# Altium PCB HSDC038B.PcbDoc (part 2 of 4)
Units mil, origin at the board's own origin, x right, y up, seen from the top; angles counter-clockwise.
Board outline 3620 x 4060 mil, 6 copper layers (Top Layer, Signal Layer 1, Signal Layer 2, Signal Layer 3, Signal Layer 4, Bottom Layer), stack 60.4 mil thick; 349 components, 209 nets, 1023 pads, 960 vias.
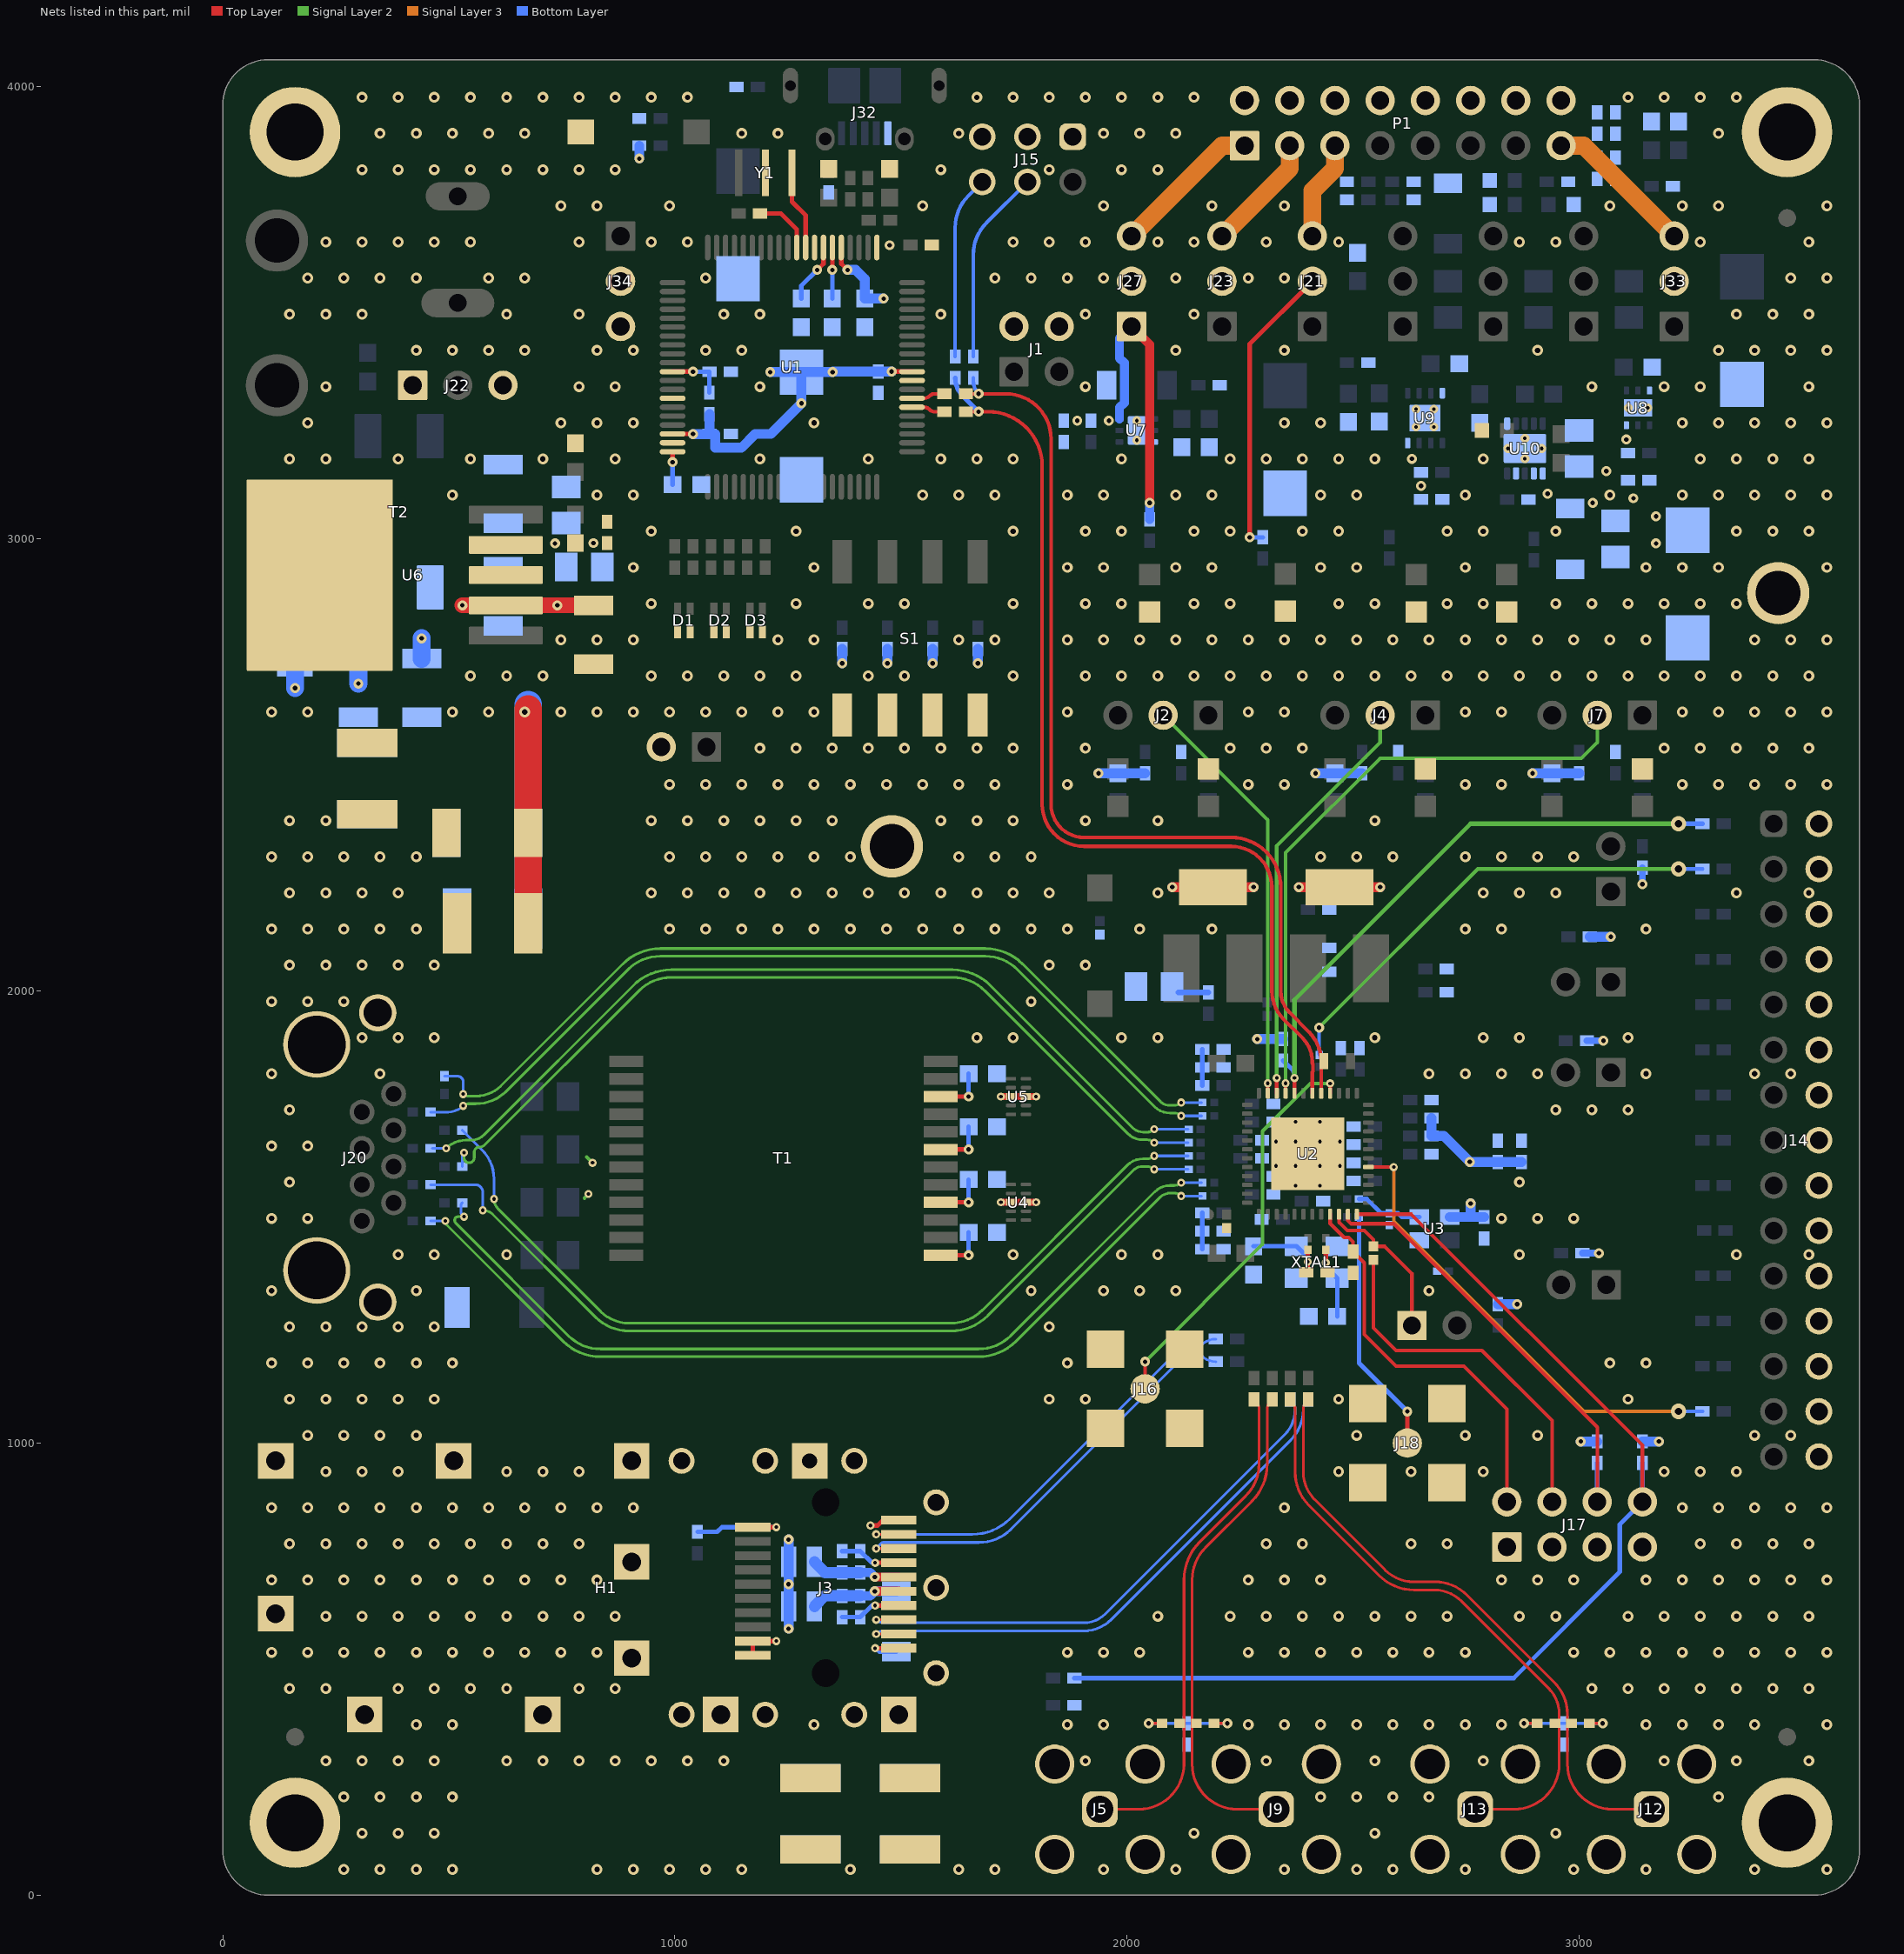
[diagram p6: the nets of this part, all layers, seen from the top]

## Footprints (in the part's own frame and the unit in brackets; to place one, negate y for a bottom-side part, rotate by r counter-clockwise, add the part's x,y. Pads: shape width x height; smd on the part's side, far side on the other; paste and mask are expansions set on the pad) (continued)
TSW-104-07-G-D [mm] "Samtec 100mil, 2x4, 230 mil above insulator"
  rrect6% 1.65x1.65 hole 1.016: 1(-3.81,-1.27)
  round 1.65 hole 1.016: 2(-3.81,1.27) 3(-1.27,-1.27) 4(-1.27,1.27) 5(1.27,-1.27) 6(1.27,1.27) 7(3.81,-1.27) 8(3.81,1.27)
  silkscreen extent -6.1,-2.54 5.08,2.54, body extent -5.08,-2.54 5.08,2.54, height 8.38
TSW-108-07-G-D [mm] "Samtec 100mil, 2x8, 230 mil above insulator"
  rrect6% 1.65x1.65 hole 1.016: 1(-8.89,-1.27)
  round 1.65 hole 1.016: 2(-8.89,1.27) 3(-6.35,-1.27) 4(-6.35,1.27) 5(-3.81,-1.27) 6(-3.81,1.27) 7(-1.27,-1.27) 8(-1.27,1.27) 9(1.27,-1.27) 10(1.27,1.27) 11(3.81,-1.27) 12(3.81,1.27) 13(6.35,-1.27) 14(6.35,1.27) 15(8.89,-1.27) 16(8.89,1.27)
  silkscreen extent -11.18,-2.54 10.16,2.54, body extent -10.16,-2.54 10.16,2.54, height 8.38
WEEE_Minimum [mil] "WEEElie bin"
  silkscreen extent -95,-172 99,104

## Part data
C1: library part CMP-0006254-2, "CAP, CERM, 1000 pF, 50 V, +/- 5%, C0G/NP0, 0402"
C2 C5: library part CMP-0007013-5, "CAP, CERM, 0.22 uF, 50 V, +/- 10%, X5R, 0603"
C3: library part CMP-0007033-4, "CAP, CERM, 0.47 uF, 50 V, +/- 10%, X6S, 0603"
C4: library part CMP-0007022-5, "CAP, CERM, 4.7 uF, 35 V, +/- 10%, X5R, 0603"
C6: library part CMP-0011855-2, "CAP, TA, 10 uF, 35 V, +/- 10%, 0.125 ohm, SMD"
C7 C8 C9 C13 C16 C75 C82 C93: library part CMP-0006641-2, "CAP, CERM, 0.1 uF, 16 V, +/- 10%, X7R, 0402"
C10 C11: library part CMP-0007074-4, "CAP, CERM, 10 pF, 50 V, +/- 5%, C0G/NP0, 0603"
C12 C14 C15 C17: library part CMP-0006204-2, "CAP, CERM, 0.1 uF, 16 V, +/- 10%, X5R, 0402"
C18 C25 C31 C35 C36: library part CMP-0006590-2, "CAP, CERM, 0.01 uF, 16 V, +/- 10%, X5R, 0402"
C19 C20 C21 C22 C28 C29 C30 C37 C38 C96 C97: library part CMP-0006259-2, "CAP, CERM, 0.1 uF, 10 V, +/- 10%, X5R, 0402"
C23 C24 C26 C27 C32 C33 C34 C39 C40 C80 C94 C95: library part CMP-0084375-1, "CAP, CERM, 1 µF, 16 V,+/- 20%, X5R, 0402"
C41: library part CMP-0079541-1, "CAP, CERM, 47 µF, 4 V,+/- 20%, X6S, 0805"
C42: library part CMP-0006236-2, "CAP, CERM, 0.01 uF, 50 V, +/- 5%, X7R, 0402"
C43: library part CMP-0006234-2, "CAP, CERM, 1000 pF, 25 V, +/- 5%, X7R, 0402"
C44 C90 C102 C107 C108 C114: library part CMP-0006303-2, "CAP, CERM, 100 pF, 50 V, +/- 5%, C0G/NP0, 0402"
C45 C46: library part CMP-0007071-4, "CAP, CERM, 22 pF, 50 V, +/- 5%, C0G/NP0, AEC-Q200 Grade 1, 0603"
C47 C48 C50 C52 C53 C55 C56 C58: library part CMP-0006574-2, "CAP, CERM, 0.033 uF, 10 V, +/- 10%, X5R, 0402"
C49 C51 C54 C57: library part CMP-0006862-2, "CAP, CERM, 0.1 uF, 10 V, +/- 10%, X7R, 0603"
C59: library part CMP-0009436-2, "CAP, CERM, 1000 pF, 2000 V, +/- 10%, X7R, 1808"
C60 C61 C62 C63 C64 C65 C66 C67: library part CMP-0009295-2, "CAP, CERM, 4700 pF, 2000 V, +/- 10%, X7R, 1812"
C68 C70 C84: library part CMP-0009155-2, "CAP, CERM, 10 uF, 25 V, +/- 20%, X7R, AEC-Q200 Grade 1, 1210"
C69 C85: library part CMP-0009154-2, "CAP, CERM, 22 uF, 16 V, +/- 20%, X7R, AEC-Q200 Grade 1, 1210"
C71: library part CMP-0008135-2, "CAP, CERM, 1 uF, 16 V, +/- 10%, X5R, 0805"
C72: library part CMP-0008021-2, "CAP, CERM, 0.1 uF, 50 V, +/- 10%, X7R, AEC-Q200 Grade 1, 0805"
C73 C74 C81: library part CMP-0006324-2, "CAP, CERM, 0.01 uF, 50 V, +/- 10%, X7R, AEC-Q200 Grade 1, 0402"
C76 C86 C106: library part CMP-0007068-4, "CAP, CERM, 2.2 uF, 16 V, +/- 20%, X7S, AEC-Q200 Grade 1, 0603"
C77 C87 C99: library part CMP-0006620-2, "CAP, CERM, 1 uF, 35 V, +/- 20%, X5R, 0402"
C78 C83 C109 C110: library part CMP-0008706-2, "CAP, CERM, 10 uF, 35 V, +/- 20%, X7R, 1206_190"
C79 C111: library part CMP-0007110-5, "CAP, CERM, 0.1 uF, 16 V, +/- 10%, X7R, 0603"
C88 C100 C105 C112: library part CMP-0006850-4, "CAP, CERM, 0.01 uF, 50 V, +/- 5%, X7R, 0603"
C89 C101 C113: library part CMP-0006764-4, "CAP, CERM, 1000 pF, 50 V, +/- 10%, C0G/NP0, 0603"
C91 C98 C115: library part CMP-0011720-2, "CAP, TA, 100 uF, 10 V, +/- 20%, 0.1 ohm, SMD"
C92: library part CMP-0011708-2, "CAP, TA, 4.7 uF, 35 V, +/- 10%, 1.3 ohm, SMD"
C103 C104: library part CMP-0006606-2, "CAP, CERM, 1000 pF, 25 V, +/- 10%, X5R, 0402"
C116: library part CMP-0007676-2, "CAP, CERM, 1 uF, 16 V, +/- 10%, X5R, 0805"
C117: library part CMP-0007960-1, "CAP, CERM, 4.7 uF, 10 V, +80/-20%, Y5V, 0805"
C118: library part CMP-0007116-4, "CAP, CERM, 27 pF, 50 V, +/- 1%, C0G/NP0, 0603"
D1 D2 D3: library part CMP-0002934-2, "LED, Rg, SMD"
D4: library part CMP-0028762-1, "Diode, Schottky, 60 V, 1 A, AEC-Q101, SMA"
D5 D6 D7 D8 LD1 LD2 LD3 LD4 LD5 LD6: library part CMP-0002917-1, "LED, Green, SMD"
F1: library part CMP-0003588-2, "Fuse, 3 A, 32 VDC, SMD"
FID1 FID2 FID3 FID4 FID5 FID6: library part CMP-0077181-1, "Fiducial mark.  There is nothing to buy or mount."
H1: library part CMP-0003774-1, "SFP Single Cage"
J1: library part CMP-0075404-1, "Header, 100mil, 2x2, Gold, TH"
J2 J4 J7 J21 J22 J23 J27 J28 J33 J34 J35 J36: library part CMP-0075484-1, "Header, 100mil, 3x1, Gold, TH"
J3: library part CMP-0054875-1, "Receptacle, 0.8mm, 10x2, Gold, R/A, SMT"
J5 J9 J12 J13: library part CMP-0055851-2, "JACK, SMA, 50 Ohm, Gold, R/A, TH"
J6 J8 J10 J11 J19 J26: library part CMP-0075483-1, "Header, 100mil, 2x1, Gold, TH"
J14: library part CMP-0080723-1, "Header, 2.54mm, 15x2, Gold, TH"
J15: library part CMP-0077741-1, "Header, 2.54mm, 3x2, Gold, R/A, TH"
J16 J18: library part CMP-0075480-1, "Mini-RFCable Connector 50 Ohm"
J17: library part CMP-0075408-1, "Header, 100mil, 4x2, Gold, TH"
J20: library part CMP-0054918-1, "RJ45, No LED, tab up, R/A, TH"
J24 J29 J30 J31: library part CMP-0055113-1, "Terminal, Turret, TH, Double"
J25: library part CMP-0075114-1, "Power Jack, 2mm, R/A, TH"
J32: library part CMP-0055301-1, "Connector, Receptacle, Micro-USB Type AB, R/A, Bottom Mount SMT"
L1 L2: library part CMP-0063209-1, "Inductor, Shielded, Ferrite, 1 uH, 1.6 A, 0.115 ohm, SMD"
LBL1: library part CMP-0003625-1, "Thermal Transfer Printable Labels, 0.650\" W x 0.200\" H - 10,000 per roll"
Logo1: library part CMP-0074844-1
Logo2: library part CMP-0074838-1, "Texas Instrument Corporate Signature"
Logo3: library part CMP-0074847-1, "FCC_disclaimer"
Logo4: library part CMP-0074769-1
M1 M2 M3 M4 TP7: library part CMP-0078143-2, "TEST POINT.  No entry in BOM."
P1: library part CMP-0075418-1, "Header, 100mil, 8x2, Gold, TH"
R1 R2 R3 R4 R5 R6 R108 R109 R110: library part CMP-0026934-3, "RES, 470, 5%, 0.063 W, AEC-Q200 Grade 0, 0402"
R7 R8 R9 R10 R19 R20 R25 R27 R30 R32 R35 R37 R41 R42 R43 R44 R88 R90 R92 R93: library part CMP-0026237-2, "RES, 2.49 k, 1%, 0.063 W, AEC-Q200 Grade 0, 0402"
R11 R15: library part CMP-0026822-3, "RES, 0, 5%, 0.063 W, AEC-Q200 Grade 0, 0402"
R12: library part CMP-0026935-3, "RES, 47 k, 5%, 0.063 W, AEC-Q200 Grade 0, 0402"
R13: library part CMP-0026085-3, "RES, 1.40 k, 1%, 0.063 W, AEC-Q200 Grade 0, 0402"
R14: library part CMP-0026100-2, "RES, 1.00 M, 1%, 0.063 W, AEC-Q200 Grade 0, 0402"
R16 R17: library part CMP-0026888-3, "RES, 27, 5%, 0.063 W, AEC-Q200 Grade 0, 0402"
R18 R21 R24 R28 R29 R36: library part CMP-0023129-3, "RES, 470, 1%, 0.1 W, 0603"
R22: library part CMP-0026992-2, "RES, 0, 5%, 0.063 W, 0402"
R23 R33 R40: library part CMP-0026512-2, "RES, 6.04 k, 1%, 0.063 W, AEC-Q200 Grade 0, 0402"
R26: library part CMP-0026938-5, "RES, 4.7 k, 5%, 0.063 W, AEC-Q200 Grade 0, 0402"
R31 R38 R45 R47 R71 R72: library part CMP-0027002-2, "RES, 0, 5%, 0.063 W, 0402"
R34 R39 R46 R48: library part CMP-0026404-2, "RES, 49.9, 1%, 0.063 W, AEC-Q200 Grade 0, 0402"
R49 R50 R51 R52 R53 R54 R55 R56 R57 R58 R59 R60 R61 R62 R76 R78 R79 R84: library part CMP-0027004-2, "RES, 0, 5%, 0.063 W, 0402"
R63 R64 R65 R66 R67 R68 R69 R70 R83 R86 R87 R89 R94 R95: library part CMP-0065361-1, "RES, 0, 5%, .05 W, AEC-Q200 Grade 0, 0201"
R73: library part CMP-0027263-3, "RES, 11.0 k, 1%, 0.05 W, 0201"
R74: library part CMP-0027015-3, "RES, 22, 5%, 0.05 W, AEC-Q200 Grade 1, 0201"
R75: library part CMP-0025690-1, "RES, 2.21 k, 0.1%, 0.1 W, AEC-Q200 Grade 0, 0603"
R77 R80: library part CMP-0027010-2, "RES, 2.2 k, 5%, 0.05 W, 0201"
R81: library part CMP-0026656-1, "RES, 100, 1%, 0.1 W, 0402"
R82: library part CMP-0026993-2, "RES, 100, 5%, 0.1 W, AEC-Q200 Grade 0, 0402"
R85: library part CMP-0027280-3, "RES, 4.70 k, 1%, 0.05 W, 0201"
R91: library part CMP-0026727-1, "RES, 1.00 M, 1%, 0.063 W, 0402"
R96 R97 R98 R99: library part CMP-0021425-2, "RES, 75.0, 1%, 0.125 W, 0805"
R100 R101: library part CMP-0016535-2, "RES, 1.00 M, 1%, 1 W, 2010"
R102: library part CMP-0022451-4, "RES, 4.22 k, 1%, 0.1 W, AEC-Q200 Grade 0, 0603"
R103: library part CMP-0023885-3, "RES, 1.35 k, 0.1%, 0.1 W, 0603"
R104 R106 R113 R116: library part CMP-0025958-3, "RES, 10.0 k, 1%, 0.063 W, AEC-Q200 Grade 0, 0402"
R105 R111 R115: library part CMP-0020616-2, "RES, 0, 5%, 0.125 W, 0805"
R107: library part CMP-0026972-3, "RES, 750, 5%, 0.063 W, AEC-Q200 Grade 0, 0402"
R112: library part CMP-0026908-3, "RES, 33, 5%, 0.063 W, AEC-Q200 Grade 0, 0402"
R114: library part CMP-0022746-3, "RES, 10.0 k, 1%, 0.1 W, 0603"
R117: library part CMP-0022114-4, "RES, 1.13 k, 1%, 0.1 W, AEC-Q200 Grade 0, 0603"
R118 R119: library part CMP-0025885-3, "RES, 0, 5%, 0.1 W, 0603"
R120: library part CMP-0022454-4, "RES, 4.53 k, 1%, 0.1 W, AEC-Q200 Grade 0, 0603"
S1: library part CMP-0002176-2, "Switch, SPST 4 Pos, Top Actuated, SMT"
S2 S3: library part CMP-0002170-2, "Switch, Normally open, 2.3N force, 200k operations, SMD"
SH1 SH2 SH3 SH4 SH5 SH6 SH7 SH8 SH9 SH10 SH11 SH12 SH13: library part CMP-0003614-1, "Shunt, 100mil, Gold plated, Black"
T1: library part CMP-0030394-2, "Transformer, 325 uH, SMT"
T2: library part CMP-0013076-2, "Coupled inductor, 5 A, 0.01 ohm, SMD"
TP1 TP2 TP3 TP4 TP5 TP6: library part CMP-0055162-1, "Test Point, Miniature, SMT"
U1: library part CMP-0038965-1, "25 MHz Mixed Signal Microcontroller with 128 KB Flash, 8192 B SRAM and 63 GPIOs, -40 to 85 degC, 80-pin QFP (PN), Green (RoHS & no Sb/Br)"
U2: library part CMP-0079810-3, "Robust, High Immunity 10/100/1000 Ethernet Physical Layer Transceiver, RGZ0048B (VQFN-48)"
U3: library part CMP-0084386-1, "Oscillator, 25 MHz, SMD"
U4 U5: library part CMP-0073613-2, "4-Channel Ultra-Low-Capacitance IEC ESD Protection Diode, DQA0010A (USON-10)"
U6: library part CMP-0036893-1, "Single Output Fast Transient Response LDO, 1.5 A, Adjustable 1.21 to 20 V Output, 2.1 to 20 V Input, 5-pin DDPAK (KTT), -40 to 125 degC, Green (RoHS & no Sb/Br)"
U7: library part CMP-0073832-4, "Single Output LDO, 1A, Adj. (1.2 to 5.0V), Reverse Current Protection, DRV0006A (WSON-6)"
U8: library part CMP-0066782-5, "150-mA, 30-V, Ultra-Low IQ, Wide Input Low-Dropout Regulator with Reverse Current Protection, DRV0006A (WSON-6)"
U9: library part CMP-0036320-2, "Single Output High PSRR LDO, 500 mA, Fixed 2.5 V Output, 2.7 to 6.5 V Input, with Low IQ, 8-pin SON (DRB), -40 to 125 degC, Green (RoHS & no Sb/Br)"
U10: library part CMP-0036362-3, "Single Output LDO, 500 mA, Adjustable 0.8 to 3.6 V Output, 0.8 to 5.5 V Input, with Programmable Soft Start, 10-pin SON (DRC), -40 to 125 degC, Green (RoHS & no Sb/Br)"
XTAL1: library part CMP-0079863-1, "Crystal, 25 MHz, 20 ppm, AEC-Q200 Grade 1, SMD"
Y1: library part CMP-0084387-1, "Resonator, 4 MHz, 39 pF, AEC-Q200 Grade 1, SMD"
ZZ1: library part CMP-0003616-3
ZZ2: library part CMP-0077236-1
ZZ3: library part CMP-0077237-1
ZZ4: library part CMP-0077238-1

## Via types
v1: diameter 24, hole 12, Top Layer to Bottom Layer, tented both sides, 728 vias
v2: diameter 22, hole 10, Top Layer to Bottom Layer, tented both sides, 113 vias
v3: diameter 17.87, hole 7.87, Top Layer to Bottom Layer, tented both sides, 67 vias
v4: diameter 19.68, hole 7.87, Top Layer to Bottom Layer, tented both sides, 24 vias
v5: diameter 34, hole 16, Top Layer to Bottom Layer, tented both sides, 15 vias
v6: diameter 18, hole 8, Top Layer to Bottom Layer, tented both sides, 13 vias

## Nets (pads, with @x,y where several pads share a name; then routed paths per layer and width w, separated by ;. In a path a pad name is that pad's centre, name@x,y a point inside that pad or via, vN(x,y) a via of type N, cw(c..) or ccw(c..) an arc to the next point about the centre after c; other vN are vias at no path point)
5V_LDO: C69.1 C70.1 C71.1 C72.1 C73.1 J34.3 R102.2 U6.4
  other v2: 735,2990 820,2990.87
5V_SUPPLY: C77.1 C87.1 C99.1 C109.2 C115.1 C116.2 C117.1 J27.1 J34.2 R104.2 R106.2 R107.2 R113.2 R116.1 U7.6 U8.6 U9.8 U10.1 U10.2 U10.4 | length 667.5
  Top Layer w20: J27.1@2010,3470 2050,3430 v2(2050,3080)
  Bottom Layer w20: U7.6@1983.23,3265.59 1983.23,3290.12 1994.21,3301.1 1994.21,3389.37 1983.23,3400.35 1983.23,3443.23 J27.1@2010,3470 ; R107.2@2050,3043.62 v2(2050,3080)
  other v2: 3170,2990 3170,3050 3030,3080 3120,3090 2930,3100 2650.2,3117.28 3060,3150 2630.2,3177.28 3104.41,3220 1890,3261.65 1960,3261.65
20V-5V: C68.1 C84.1 C85.1 D4.1 J22.3 J26.2 U6.2 | length 455.2
  Top Layer w35: v2(530,2853.07) U6.2@626.06,2853.07 v2(740,2853.07) C68.1@820,2853.07
  Bottom Layer w40: v2(160,2670) D4.1@160,2735.2 ; v2(300,2680) C84.1@300,2735.2 ; C85.1@440,2735.2 v2(440,2780)
25M_REF: R85.2 R95.2 U3.3 | length 150.1
  Bottom Layer w10: R95.2@2512.99,1540 2530,1540 2561.97,1508.03 R85.2@2580,1508.03 2599.8,1508.03 2607.83,1500 U3.3@2646.54,1500
AUX_IOVDD: C42.2 C43.2 C44.2 J33.2 R18.1 R19.2 R24.1 R25.2 R29.1 R30.2 R32.2 R33.2 R35.2 R40.2 R42.2 R44.2 R88.2 R90.2 R92.2 R93.2 U3.4 | length 1006.4
  Bottom Layer w15: R30.2@3007.24,1420 v2(3043.62,1420) ; R42.2@3017.24,1890 v2(3053.62,1890) ; v2(3140,2236.38) R35.2@3140,2272.76
  Bottom Layer w22: v2(1936.84,2481.5) R18.1@1980,2481.5 R19.2@2040,2481.5 ; v2(2288,1893.62) R88.2@2345,1893.62 ; v2(2416.84,2481.5) R24.1@2460,2481.5 R25.2@2520,2481.5 ; R40.2@2673.62,1718.9 R33.2@2673.62,1679.21 2700.79,1679.21 v2(2757.9,1622.1) 2819.36,1622.1 C42.2@2820,1621.46 C43.2@2872.42,1621.46 ; U3.4@2713.46,1500 2760,1500 ; v2(2760,1530) 2760,1500 ; C44.2@2790,1500 2760,1500 ; R93.2@2820,1307.24 v2(2862.76,1307.24) ; v2(2896.84,2481.5) R29.1@2940,2481.5 R32.2@3000,2481.5 ; v2(3003.62,1003.62) R90.2@3040,1003.62 ; R44.2@3023.62,2120 v2(3070,2120) ; R92.2@3140,1003.62 v2(3176.38,1003.62)
AUX_IOVDD_EXT: C94.2 C96.2 C103.2 C107.2 J33.3 P1.15 | length 332.8
  Signal Layer 3 w40: P1.15@2960,3870 3010,3870 J33.3@3210,3670
CAP_TD_A_N: C56.2 R64.2 | length 1976.2
  Signal Layer 2 w6: v3(532,1746) cw(c542.86,1735.14) 542.86,1750.5 560,1750.5 ccw(c560,1845.86) 627.43,1778.43 896.71,2047.71 cw(c967.42,1977) 967.42,2077 1686.59,2077 cw(c1686.59,1977) 1757.3,2047.71 2061.02,1744 ccw(c2095,1778) 2095,1729.93 2104.69,1729.93 cw(c2104.69,1708.27) v3(2120,1723.58)
  Bottom Layer w6: C56.2@459.69,1732.17 498.6,1732.17 ccw(c498.6,1779.4) v3(532,1746) ; v3(2120,1723.58) R64.2@2165.04,1723.58
CAP_TD_A_P: C58.2 R63.2 | length 1975.9
  Signal Layer 2 w6: v3(532,1772) ccw(c542.86,1782.86) 542.86,1767.5 560,1767.5 ccw(c560,1845.86) 615.41,1790.45 884.69,2059.73 cw(c967.42,1977) 967.42,2094 1686.59,2094 cw(c1686.59,1977) 1769.32,2059.73 2073.03,1756.03 ccw(c2095,1778) 2095,1746.93 2104.69,1746.93 ccw(c2104.69,1768.58) v3(2120,1753.27)
  Bottom Layer w6: C58.2@490.39,1811.69 519,1811.69 cw(c519,1798.69) 532,1798.69 v3(532,1772) ; v3(2120,1753.27) R63.2@2165.04,1753.27
CAP_TD_B_N: C53.2 R66.2 | length 1970.1
  Signal Layer 2 w6: v3(533.7,1642.38) 533.7,1631.3 ccw(c545,1631.3) 545,1620 ccw(c545,1631.3) 556.3,1631.3 556.3,1643.3 cw(c568,1643.3) 568,1655 ccw(c568,1672) 580.02,1659.98 589.33,1669.29 920.75,2000.71 cw(c991.46,1930) 991.46,2030 1614.54,2030 cw(c1614.54,1930) 1685.25,2000.71 2001.02,1684.94 ccw(c2035,1718.94) 2035,1670.87 2044.69,1670.87 cw(c2044.69,1649.22) v3(2060,1664.53)
  Bottom Layer w6: C53.2@529.76,1611.69 529.76,1632.88 cw(c543.21,1632.88) v3(533.7,1642.38) ; v3(2060,1664.53) R66.2@2135.04,1664.53
CAP_TD_B_P: C55.2 R65.2 | length 1969.8
  Signal Layer 2 w6: v3(494.31,1651.85) cw(c538.13,1608.03) 538.13,1670 550,1670 ccw(c550,1708.63) 577.31,1681.31 908.73,2012.73 cw(c991.46,1930) 991.46,2047 1614.54,2047 cw(c1614.54,1930) 1697.27,2012.73 2013.03,1696.97 ccw(c2035,1718.94) 2035,1687.87 2044.69,1687.87 ccw(c2044.69,1709.52) v3(2060,1694.21)
  Bottom Layer w6: C55.2@463.62,1651.85 v3(494.31,1651.85) ; v3(2060,1694.21) R65.2@2135.04,1694.21
CAP_TD_C_N: C50.2 R68.2 | length 1975.6
  Signal Layer 2 w6: v3(575,1515) cw(c575,1483.67) 597.16,1505.82 823.99,1278.99 ccw(c898.81,1353.81) 898.81,1248 1609.85,1248 ccw(c1609.85,1365) 1692.58,1282.27 2013.03,1602.71 cw(c2035,1580.74) 2035,1611.81 2044.69,1611.81 cw(c2044.69,1590.16) v3(2060,1605.47)
  Bottom Layer w6: C50.2@459.69,1571.54 558.73,1571.54 cw(c558.73,1555.27) 575,1555.27 v3(575,1515) ; v3(2060,1605.47) R68.2@2135.04,1605.47
CAP_TD_C_P: C52.2 R67.2 | length 1974.6
  Signal Layer 2 w6: v3(600,1540) ccw(c631.33,1540) 609.18,1517.84 836.01,1291.01 ccw(c898.81,1353.81) 898.81,1265 1609.85,1265 ccw(c1609.85,1365) 1680.56,1294.29 2001.02,1614.74 cw(c2035,1580.74) 2035,1628.81 2044.69,1628.81 ccw(c2044.69,1650.47) v3(2060,1635.16)
  Bottom Layer w6: C52.2@529.76,1692.01 573.49,1648.28 cw(c509.5,1584.29) 600,1584.29 v3(600,1540) ; v3(2060,1635.16) R67.2@2135.04,1635.16
CAP_TD_D_N: C47.2 R70.2 | length 1972.5
  Signal Layer 2 w6: v3(492.31,1491.22) ccw(c505.77,1491.22) 496.26,1481.7 752.69,1225.27 ccw(c835.42,1308) 835.42,1191 1671.91,1191 ccw(c1671.91,1308) 1754.64,1225.27 2073.03,1543.66 cw(c2095,1521.69) 2095,1552.76 2104.69,1552.76 cw(c2104.69,1531.11) v3(2120,1546.42)
  Bottom Layer w6: C47.2@459.69,1491.22 v3(492.31,1491.22) ; v3(2120,1546.42) R70.2@2165.04,1546.42
CAP_TD_D_P: C48.2 R69.2 | length 1971.9
  Signal Layer 2 w6: v3(533.7,1500.69) 520.47,1500.69 ccw(c520.47,1493.22) 513,1493.22 ccw(c523.19,1493.22) 515.98,1486.02 764.71,1237.29 ccw(c835.42,1308) 835.42,1208 1671.91,1208 ccw(c1671.91,1308) 1742.62,1237.29 2061.02,1555.69 cw(c2095,1521.69) 2095,1569.76 2104.69,1569.76 ccw(c2104.69,1591.41) v3(2120,1576.1)
  Bottom Layer w6: C48.2@529.76,1531.38 ccw(c536.44,1524.71) 527,1524.71 527,1511 ccw(c535.72,1511) 529.55,1504.84 v3(533.7,1500.69) ; v3(2120,1576.1) R69.2@2165.04,1576.1
CLKOUT: J16.1 U2.40 | length 892.3
  Top Layer w8: J16.1@2040,1120 v2(2040,1180) ; U2.40@2449.21,1773.86 v3(2449.21,1795.56)
  Signal Layer 2 w8: v2(2040,1180) 2300,1440 2300,1690 2405.56,1795.56 v3(2449.21,1795.56)
CONN_SI_N: C15.1 J12.1 R46.2 | length 1351.8
  Top Layer w6: 2389.79,935.87 ccw(c2475.87,935.87) 2414.99,875.01 2570.13,719.87 ccw(c2635,784.74) 2635,693 2681.03,693 cw(c2681.03,593) 2751.75,663.71 2944.71,470.75 cw(c2874,400.03) 2974,400.03 2974,290 ccw(c3074,290) 3074,190 J12.1@3160,190 ; 2389.79,936.13 2389.79,1074.06 cw(c2417.1,1074.06) C15.1@2397.78,1093.37 ; C15.1@2397.79,1093.38 C15.1@2400.79,1096.38
CONN_SI_P: C17.1 J13.1 R48.1 | length 1351.9
  Top Layer w6: C17.1@2360.79,1096.38 C17.1@2363.79,1093.38 ; C17.1@2363.8,1093.37 cw(c2344.47,1074.06) 2371.79,1074.06 2371.79,935.87 ccw(c2475.87,935.87) 2402.27,862.27 2557.4,707.14 ccw(c2635,784.74) 2635,675 2679.64,675 cw(c2679.64,589.64) 2740,650 2931.96,458.04 cw(c2873.92,400) 2956,400 2956,290 cw(c2856,290) 2856,190 J13.1@2770,190
Conn_SO_N: C12.1 J5.1 R34.2 | length 1112.3
  Top Layer w6: J5.1@1940,190 2026,190 ccw(c2026,290) 2126,290 2126,697.58 cw(c2244,697.58) 2160.56,781.01 2262.81,883.27 ccw(c2192.1,953.98) 2292.1,953.98 2292.1,1074.06 ccw(c2264.79,1074.06) C12.1@2284.11,1093.37 ; C12.1@2281.1,1096.38 C12.1@2284.1,1093.38
Conn_SO_P: C14.1 J9.1 R39.1 | length 1112.3
  Top Layer w6: C14.1@2318.09,1093.37 ccw(c2337.42,1074.06) 2310.1,1074.06 2310.1,953.98 cw(c2192.1,953.98) 2275.55,870.55 2173.29,768.29 ccw(c2244,697.58) 2144,697.58 2144,290 ccw(c2244,290) 2244,190 J9.1@2330,190 ; C14.1@2318.1,1093.38 C14.1@2321.1,1096.38
EARTH_GND: C59.2 C60.2 C61.2 C62.2 C63.2 C64.2 C65.2 C66.2 C67.2 H1.1 H1.2 H1.3 H1.4 H1.5 H1.6 H1.7 H1.8 H1.9 H1.10 H1.11 H1.12 H1.MH1 H1.MH2 H1.MH3 H1.MH4 H1.MH5 H1.MH6 H1.MH7 H1.MH8 J20.9 J20.10 J20.11 J20.12 M1.1 R100.1 R101.1 | length 30.8
  Signal Layer 2 w8: 800,1542 v3(809,1551) ; 805.23,1632.77 v3(818,1620)
  other v1: 268,57 348,57 428,57 508,57 308,137 388,137 468,137 268,217 348,217 428,217 508,217 228,297 308,297 388,297 468,297 628,297 708,297 788,297 868,297 948,297 1028,297 1108,297 428,377 508,377 1308,377 148,457 228,457 388,457 468,457 548,457 628,457 788,457 868,457 108,537 188,537 268,537 348,537 428,537 508,537 588,537 668,537 748,537 828,537 228,617 308,617 388,617 468,617 548,617 628,617 708,617 788,617 868,617 108,697 188,697 268,697 348,697 428,697 508,697 588,697 668,697 748,697 828,697 148,777 228,777 308,777 388,777 468,777 548,777 628,777 708,777 788,777 108,857 188,857 268,857 348,857 428,857 508,857 588,857 668,857 748,857 828,857 908,857 228,937 308,937 388,937 628,937 708,937 788,937 188,1017 268,1017 348,1017 428,1017 148,1097 228,1097 308,1097 388,1097 468,1097 108,1177 188,1177 268,1177 348,1177 428,1177 508,1177 148,1257 228,1257 308,1257 388,1257 468,1257 108,1337 428,1337 388,1417 468,1417 628,1417 108,1497 188,1497 148,1577 108,1657 188,1657 148,1737 108,1817 348,1817 308,1897 388,1897 468,1897 108,1977 188,1977 268,1977 148,2057 228,2057 308,2057 388,2057 468,2057 108,2137 188,2137 268,2137 348,2137 428,2137 148,2217 228,2217 308,2217 388,2217 108,2297 188,2297 268,2297 348,2297 428,2297 148,2377 228,2377
EXT_REF_CLK: J18.1 R94.1 | length 544.3
  Top Layer w10: J18.1@2620,1000 v2(2620,1070)
  Bottom Layer w10: R94.1@2512.99,1500 2512.99,1177.01 v2(2620,1070)
EXT_RESET_N: R50.2 R83.1 | length 1051.9
  Signal Layer 2 w8: v2(2425,1919.07) 2775.93,2270 v5(3220,2270)
  Bottom Layer w8: R83.1@2425,1860.24 v2(2425,1919.07) ; v5(3220,2270) R50.2@3272.76,2270
FX3V3: J21.2 L1.1 L2.1 R108.2 | length 849.9
  Top Layer w10: v2(2271.38,3003.62) 2271.38,3431.38 J21.2@2410,3570
  Bottom Layer w10: v2(2271.38,3003.62) R108.2@2300,3003.62
  Bottom Layer w22: v2(1251.46,589.13) L2.1@1251.46,638.5 v2(1251.46,687.87) L1.1@1251.46,737.24 v2(1251.46,786.61)
FX3V3_EXT: J21.3 P1.5 | length 220.7
  Signal Layer 3 w40: J21.3@2410,3670 2410,3770 2460,3820 P1.5@2460,3870
FX_SI_N: J3.12 R45.2 | length 1240
  Top Layer w6: v3(1445.35,577.64) J3.12@1495.12,577.64
  Bottom Layer w6: v3(1445.35,577.64) cw(c1461.64,561.35) 1461.64,584.39 1903.94,584.39 ccw(c1903.94,671.06) 1965.23,609.77 2361.69,1006.24 ccw(c2293.86,1074.06) 2389.79,1074.06 cw(c2417.1,1074.06) R45.2@2397.78,1093.37 ; R45.2@2397.79,1093.38 R45.2@2400.79,1096.38
FX_SI_P: J3.13 R47.2 | length 1211.3
  Top Layer w6: v3(1445.35,609.13) J3.13@1495.12,609.13
  Bottom Layer w6: v3(1445.35,609.13) ccw(c1461.64,625.43) 1461.64,602.39 1903.59,602.39 ; 1903.94,602.39 ccw(c1903.94,671.06) 1952.5,622.5 2348.96,1018.96 ccw(c2293.86,1074.06) 2371.79,1074.06 ccw(c2344.47,1074.06) R47.2@2363.8,1093.37 ; R47.2@2360.79,1096.38 R47.2@2363.79,1093.38
FX_SO_N: J3.19 R31.2 | length 971.6
  Top Layer w6: v3(1445.35,798.11) J3.19@1495.12,798.11
  Bottom Layer w6: v3(1445.35,798.11) 1445.46,798 1657.67,798 ccw(c1657.67,916) 1741.1,832.56 2117.27,1208.73 ; 2117.28,1208.73 cw(c2130,1196) 2130,1214 2157.75,1214 ccw(c2157.75,1223.37) 2164.37,1216.74 cw(c2196.38,1184.74) R31.2@2196.38,1230
FX_SO_P: J3.18 R38.2 | length 978.5
  Top Layer w6: v3(1445.35,766.61) J3.18@1495.12,766.61
  Bottom Layer w6: v3(1445.35,766.61) 1457.84,779.1 cw(c1460,776.94) 1460,780 1672.58,780 ccw(c1672.58,880) 1743.29,809.29 2130,1196 2157.75,1196 cw(c2157.75,1186.63) 2164.37,1193.26 ccw(c2196.38,1225.26) R38.2@2196.38,1180
FXVCCR: C81.1 C82.1 C83.1 J3.15 L2.2 | length 248.4
  Top Layer w20: v2(1442.13,672.13) J3.15@1495.12,672.13
  Bottom Layer w20: C81.1@1410,662.13 1432.13,662.13 v2(1442.13,672.13)
  Bottom Layer w22: v2(1442.13,672.13) C83.1@1490,672.13
  Bottom Layer w25: L2.2@1308.54,638.5 1332.17,662.13 C82.1@1370,662.13 C81.1@1410,662.13
FXVCCT: C74.1 C75.1 J3.16 L1.2 | length 200.5
  Top Layer w20: v2(1442.13,703.62) J3.16@1495.12,703.62
  Bottom Layer w20: C74.1@1410,713.62 1432.13,713.62 v2(1442.13,703.62)
  Bottom Layer w25: L1.2@1308.54,737.24 1332.17,713.62 C75.1@1370,713.62 C74.1@1410,713.62
GND: C1.1 C2.2 C3.2 C4.1 C5.2 C6.2 C7.1 C8.1 C9.1 C10.1 C11.1 C13.2 C16.2 C18.2 C19.2 C20.2 C21.2 C22.2 C23.2 C24.2 C25.2 C26.2 C27.2 C28.2 C29.2 C30.2 C31.2 C32.2 C33.2 C34.2 C35.2 C36.2 C37.2 C38.2 C39.2 C40.2 C41.2 C42.1 C43.1 C44.1 C45.2 C46.2 C49.1 C51.1 C54.1 C57.1 C60.1 C61.1 C62.1 C63.1 C64.1 C65.1 C66.1 C67.1 C68.2 C69.2 C70.2 C71.2 C72.2 C73.2 C74.2 C75.2 C76.1 C77.2 C78.2 C79.2 C80.2 C81.2 C82.2 C83.2 C84.2 C85.2 C86.1 C87.2 C88.1 C89.1 C90.1 C91.2 C92.2 C93.1 C94.1 C95.1 C96.1 C97.1 C98.2 C99.2 C100.1 C101.1 C102.1 C103.1 C104.1 C105.1 C106.1 C107.1 C108.1 C109.1 C110.2 C111.2 C112.1 C113.1 C114.1 C115.2 C116.1 C117.2 C118.1 D1.3 D1.4 D2.3 D2.4 D3.3 D3.4 D5.2 D6.2 D7.2 D8.2 J1.2 J1.4 J3.1 J3.9 J3.10 J3.11 J3.14 J3.17 J3.20 J5.2 J5.3 J5.4 J5.5 J9.2 J9.3 J9.4 J9.5 J12.2 J12.3 J12.4 J12.5 J13.2 J13.3 J13.4 J13.5 J14.2 J14.4 J14.6 J14.8 J14.10 J14.12 J14.14 J14.16 J14.18 J14.20 J14.22 J14.24 J14.26 J14.28 J14.30 J15.1 J15.3 J15.5 J16.2 J16.3 J16.4 J16.5 J17.1 J17.3 J17.5 J17.7 J18.2 J18.3 J18.4 J18.5 J22.1 J30.1 J31.1 J32.5 LD2.2 LD4.2 LD6.2 M2.1 M3.1 M4.1 P1.2 P1.4 P1.6 P1.8 P1.10 P1.12 P1.14 P1.16 R14.2 R20.1 R23.1 R26.1 R27.1 R37.1 R41.1 R43.1 R73.1 R80.1 R81.2 R85.1 R87.2 R100.2 R101.2 R103.1 R112.2 R120.1 S1.5 S1.6 S1.7 S1.8 S2.1 T2.3 TP1.1 TP2.1 U1.14 U1.19 U1.49 U1.61 U1.68 U2.49@2400,1640 U3.2 U4.3@1743.56,1532.56 U4.8@1776.44,1532.56 U5.3@1743.56,1766.42 U5.8@1776.44,1766.42 U6.3 U6.6 U7.3 U7.7@2021.61,3240 U8.3 U8.7@3130,3290 U9.4 U9.9 U10.6 U10.11@2880,3200 XTAL1.2 XTAL1.4 Y1.2 | length 2217.6
  Top Layer w10: J3.10@1172.28,530.39 J3.9@1172.28,561.89 v3(1224.35,561.89) ; J3.1@1172.28,813.86 v3(1224.35,813.86) ; v3(1432.67,817.6) 1448.59,817.6 1460.6,829.61 J3.20@1495.12,829.61 ; v3(1443.06,546.14) J3.11@1495.12,546.14 ; v3(1443.06,640.63) J3.14@1495.12,640.63 ; v3(1443.06,735.12) J3.17@1495.12,735.12
  Top Layer w15: v3(1721.1,1532.56) U4.3@1743.56,1532.56 U4.8@1776.44,1532.56 v3(1798.9,1532.56) ; v3(1721.1,1766.42) U5.3@1743.56,1766.42 U5.8@1776.44,1766.42 v3(1798.9,1766.42)
  Top Layer w22: v2(2100,2230) TP2.1@2190,2230 v2(2280,2230) ; v2(2380,2230) TP1.1@2470,2230 v2(2560,2230)
  Top Layer w60: C66.1@675.74,2150 R100.2@675.74,2350 v1@675.74,2624.26
  Bottom Layer w10: R26.1@1050,803.62 1093.62,803.62 1103.86,813.86 v3(1224.35,813.86) ; C82.2@1370,614.88 C81.2@1410,614.88 1435.75,640.63 v3(1443.06,640.63) ; C75.2@1370,760.87 C74.2@1410,760.87 1435.75,735.12 v3(1443.06,735.12) ; v3@1445.06,546.14 1452.93,538.27 C83.2@1490,538.27
  Bottom Layer w60: C67.1@675.74,2160 675.74,2634.26
  other v1: 828,57 908,57 988,57 1068,57 1148,57 1388,57 1628,57 1708,57 1948,57 2108,57 2348,57 2508,57 2588,57 2748,57 2988,57 3148,57 3388,57 3548,57 2148,137 2548,137 2948,137 2428,217 2508,217 2588,217 2668,217 3308,217 1908,297 2308,297 2548,297 2788,297 3188,297 3348,297 3508,297 1868,377 1948,377 2268,377 2348,377 2428,377 2508,377 2588,377 2668,377 2748,377 2828,377 3148,377 3228,377 3308,377 3388,377 3548,377 3028,457 3108,457 3188,457 3268,457 3348,457 3428,457 3508,457 1868,537 1948,537 2028,537 2268,537 2348,537 2428,537 2508,537 2588,537 2668,537 2748,537 2988,537 3068,537 3148,537 3228,537 3308,537 3388,537 3468,537 3548,537 2068,617 2228,617 2308,617 2388,617 2468,617 2548,617 2628,617 2708,617 2868,617 2948,617 3108,617 3188,617 3268,617 3348,617 3428,617 3508,617 2268,697 2348,697 2428,697 2828,697 2908,697 2988,697 3148,697 3228,697 3308,697 3388,697 3468,697 3548,697 2308,777 2388,777 2628,777 2708,777 3268,777 3348,777 3428,777 3508,777 2348,857 3228,857 3308,857 3388,857 3468,857 3548,857 2468,937 2628,937 2788,937 3188,937 3268,937 3348,937 2508,1017 2748,1017 2908,1017 3388,1017 3468,1017 1828,1097 1908,1097 2468,1097 3108,1097 1868,1177 3068,1177 3148,1177 1828,1257 1788,1337 1948,1337 2028,1337 2108,1337 2668,1337 1748,1417 1988,1417 2068,1417 2868,1417 3348,1417 3508,1417 2828,1497 2908,1497 2988,1497 2868,1577 2948,1737 3028,1737 3108,1737 2668,1817 2748,1817 2828,1817 2908,1817 3148,1817 3388,1817 3468,1817 1668,1897 1748,1897 1988,1897 2068,1897 2548,1897 2788,1897 2868,1897 3108,1897 1788,1977 1828,2057 1908,2057 988,2137 1068,2137 1148,2137 1228,2137 1308,2137 1388,2137 1468,2137 1548,2137 1628,2137 1708,2137 1788,2137 1868,2137 2028,2137 2188,2137 2748,2137 2828,2137 3148,2137 948,2217 1028,2217 1108,2217 1188,2217 1268,2217 1348,2217 1428,2217 1508,2217 1588,2217 1668,2217 1748,2217 1828,2217 2068,2217 2788,2217 2868,2217 2948,2217 3348,2217 3508,2217 988,2297 1068,2297 1148,2297 1228,2297 1308,2297 1388,2297 1628,2297 1708,2297 1788,2297 2428,2297 2508,2297 2588,2297 2748,2297 2828,2297 2908,2297 2988,2297 948,2377 1028,2377 1108,2377 1188,2377 1268,2377 1348,2377 1588,2377 1668,2377 1748,2377 1908,2377 2068,2377 2548,2377 988,2457 1068,2457 1148,2457 1228,2457 1308,2457 1388,2457 1468,2457 1548,2457 1628,2457 1708,2457 1868,2457 2268,2457 2348,2457 2748,2457 2828,2457 3228,2457 3308,2457 3388,2457 3468,2457 3548,2457 1188,2537 1268,2537 1348,2537 1428,2537 1508,2537 1588,2537 1668,2537 1748,2537 1908,2537 2228,2537 2308,2537 2388,2537 3188,2537 3268,2537 3348,2537 3428,2537 3508,2537 108,2617 188,2617 508,2617 588,2617 668,2617 748,2617 828,2617 908,2617 988,2617 1068,2617 1148,2617 1228,2617 1308,2617 1868,2617 2268,2617 2348,2617 2748,2617 2828,2617 3228,2617 3308,2617 3388,2617 3468,2617 3548,2617 548,2697 628,2697 708,2697 948,2697 1028,2697 1108,2697 1188,2697 1268,2697 1428,2697 1508,2697 1748,2697 1908,2697 1988,2697 2068,2697 2148,2697 2228,2697 2308,2697 2388,2697 2468,2697 2548,2697 2628,2697 2708,2697 2788,2697 2868,2697 2948,2697 3028,2697 3108,2697 3188,2697 3268,2697 3348,2697 3428,2697 3508,2697 748,2777 828,2777 908,2777 1228,2777 1308,2777 1628,2777 1708,2777 1868,2777 1948,2777 2028,2777 2108,2777 2188,2777 2268,2777 2348,2777 2428,2777 2508,2777 2588,2777 2668,2777 2748,2777 2828,2777 2908,2777 2988,2777 3068,2777 3148,2777 3388,2777 3468,2777 3548,2777 948,2857 1268,2857 1428,2857 1508,2857 1748,2857 1908,2857 1988,2857 2148,2857 2228,2857 2468,2857 2548,2857 2708,2857 2788,2857 2948,2857 3028,2857 3108,2857 3188,2857 3268,2857 3348,2857 908,2937 1308,2937 1868,2937 1948,2937 2108,2937 2188,2937 2428,2937 2508,2937 2748,2937 3148,2937 3228,2937 3308,2937 3548,2937 948,3017 1268,3017 1748,3017 1908,3017 1988,3017 2148,3017 2228,3017 2388,3017 2468,3017 2708,3017 2788,3017 2948,3017 3348,3017 3428,3017 3508,3017 508,3097 828,3097 908,3097 1548,3097 1628,3097 1708,3097 1868,3097 1948,3097 2108,3097 2188,3097 2428,3097 2508,3097 2748,3097 3068,3097 3228,3097 3308,3097 3388,3097 3468,3097 3548,3097 148,3177 228,3177 388,3177 548,3177 708,3177 868,3177 1188,3177 1428,3177 1588,3177 1668,3177 1748,3177 1988,3177 2228,3177 2308,3177 2388,3177 2468,3177 2548,3177 2788,3177 3268,3177 3348,3177 3428,3177 3508,3177 188,3257 748,3257 828,3257 908,3257 1308,3257 2348,3257 2428,3257 3228,3257 3308,3257 3388,3257 3468,3257 3548,3257 228,3337 788,3337 868,3337 1188,3337 1908,3337 3028,3337 3188,3337 3268,3337 3508,3337 428,3417 508,3417 588,3417 668,3417 828,3417 908,3417 1068,3417 1148,3417 2108,3417 2348,3417 2908,3417 3308,3417 3388,3417 3468,3417 3548,3417 148,3497 228,3497 308,3497 628,3497 788,3497 1108,3497 1188,3497 1588,3497 1908,3497 2148,3497 3348,3497 3428,3497 3508,3497 188,3577 268,3577 348,3577 428,3577 588,3577 668,3577 1068,3577 1708,3577 1788,3577 1868,3577 1948,3577 2108,3577 2268,3577 2348,3577 3468,3577 3548,3577 228,3657 308,3657 388,3657 468,3657 548,3657 788,3657 948,3657 1028,3657 1748,3657 1828,3657 1908,3657 2068,3657 2148,3657 2308,3657 2468,3657 2868,3657 2948,3657 3268,3657 3508,3657 748,3737 828,3737 988,3737 1548,3737 1948,3737 2188,3737 2348,3737 3068,3737 3228,3737 3308,3737 3548,3737 308,3817 388,3817 468,3817 548,3817 628,3817 708,3817 788,3817 868,3817 1588,3817 1828,3817 1988,3817 2068,3817 348,3897 428,3897 508,3897 588,3897 668,3897 1148,3897 1228,3897 1628,3897 1948,3897 2028,3897 2108,3897 3308,3897 308,3977 388,3977 468,3977 548,3977 628,3977 708,3977 788,3977 868,3977 948,3977 1028,3977 1668,3977 1748,3977 1828,3977 1908,3977 1988,3977 2068,3977 2148,3977 3108,3977 3188,3977 3268,3977 3348,3977
  other v2: 1474.96,3649.76
  other v4: 2373.03,1569.13 2426.97,1569.13 2329.13,1613.03 2373.03,1613.03 2426.97,1613.03 2470.87,1613.03 2329.13,1666.97 2373.03,1666.97 2426.97,1666.97 2470.87,1666.97 2373.03,1710.87 2426.97,1710.87 2880,3177.36 2842.6,3200 2917.4,3200 2021.61,3218.35 2880,3222.64 2639.37,3247.6 2678.74,3247.6 2021.61,3261.65 2639.37,3286.97 2678.74,3286.97 3108.35,3290 3151.65,3290
GTX_CLK: R62.2 U2.29 | length 1033.3
  Top Layer w8: U2.29@2533.86,1610.47 v6(2590,1610.47)
  Signal Layer 3 w8: v6(2590,1610.47) 2590,1490 3010,1070 v5(3220,1070)
  Bottom Layer w8: v5(3220,1070) R62.2@3272.76,1070
INT_PWDN: R49.2 R88.1 U2.44 | length 1329.6
  Top Layer w8: U2.44@2370.47,1773.86 v3(2370.47,1807.56)
  Signal Layer 2 w10: v3(2370.47,1807.56) 2370.47,1980.47 2760,2370 v5(3220,2370) v5@3230,2370
  Bottom Layer w10: R88.1@2345,1846.38 2368.35,1823.03 2368.35,1821.28 2370.47,1819.15 v3(2370.47,1807.56) ; v5(3220,2370) R49.2@3272.76,2370
JTAG_CLK: J17.2 R81.1 U2.21 | length 891.7
  Top Layer w8: U2.21@2449.21,1506.14 2449.21,1485.79 2480,1455 2490,1455 2500,1445 R81.1@2500,1423.62 2525,1398.62 2525,1240 2595,1170 2745,1170 2840,1075 J17.2@2840,870
JTAG_TDI: J17.8 R22.2 R92.1 U2.24 | length 2534.3
  Top Layer w8: U2.24@2508.27,1506.14 2628.86,1506.14 3140,995 J17.8@3140,870
  Bottom Layer w10: R22.2@1883.62,480 2855,480 3090,715 3090,820 J17.8@3140,870 R92.1@3140,956.38
JTAG_TDO: J19.1 R74.1 U2.22 | length 349.8
  Top Layer w8: U2.22@2468.9,1506.14 2468.9,1488.1 2487,1470 2525,1470 2545,1450 R74.1@2545,1434.96 2570.04,1434.96 2630,1375 J19.1@2630,1260
JTAG_TDO_OUT: J17.4 R74.2 | length 810
  Top Layer w8: R74.2@2545,1405.04 2545,1255 2595,1205 2785,1205 2940,1050 J17.4@2940,870
JTAG_TMS: J17.6 R90.1 U2.23 | length 1006.1
  Top Layer w8: U2.23@2488.58,1506.14 2488.58,1492.2 2495.79,1485 2590,1485 3040,1035 J17.6@3040,870
  Bottom Layer w10: J17.6@3040,870 R90.1@3040,956.38
LED_0: J2.2 U2.47 | length 932
  Top Layer w8: U2.47@2311.42,1773.86 v3(2311.42,1795.84)
  Signal Layer 2 w8: J2.2@2080,2610 2311.42,2378.58 v3(2311.42,1795.84)
LED_1: J4.2 U2.46 | length 931
  Top Layer w8: U2.46@2331.1,1773.86 v3(2331.1,1807.56)
  Signal Layer 2 w8: v3(2331.1,1807.56) 2331.1,2321.1 2560,2550 J4.2@2560,2610
LED_2: J7.2 U2.45 | length 1382.3
  Top Layer w8: U2.45@2350.79,1773.86 v3(2350.79,1795.84)
  Signal Layer 2 w8: v3(2350.79,1795.84) 2350.79,2305.79 2560,2515 3005,2515 3040,2550 J7.2@3040,2610
MCU_VBUS: C4.2 J27.2 U1.65 | length 187.2
  Top Layer w10: U1.65@1368.03,3644.76 1368.03,3608.9 v2(1381.93,3595)
  Bottom Layer w22: v2(1381.93,3595) 1400,3595 1419.77,3575.23 C4.2@1419.77,3531.5 v2(1461.7,3531.5)
MCU_VBUS_EXT: J27.3 P1.1 | length 332.8
  Signal Layer 3 w40: J27.3@2010,3670 2210,3870 P1.1@2260,3870
MCU_VCC: C6.1 C7.2 C8.2 J23.2 R7.1 R8.1 R9.1 R10.1 R12.1 R15.1 U1.18 U1.50 | length 937.4
  Top Layer w10: U1.18@995,3232.36 v2@1039.84,3232.36 ; v2@1479.69,3370.16 U1.50@1524.53,3370.16
  Bottom Layer w22: v2(921.38,3841.38) R12.1@921.38,3870 ; v2(1040,3232.2) C8.2@1076.38,3232.2 ; R15.1@1076.38,3276.38 C8.2@1076.38,3232.36 1089,3232.36 1089,3201.68 1147.19,3201.68 1177.87,3232.36 1212.36,3232.36 v2(1280,3300) C6.1@1280,3369.09 ; v2(1210.91,3369.09) C6.1@1280,3369.09 ; v2(1370,2725) R10.1@1370,2756.38 ; v2(1470,2725) R9.1@1470,2756.38 ; v2(1479.53,3370.31) C7.2@1450,3370.16 1350.16,3370.16 v2(1349.09,3369.09) C6.1@1280,3369.09 ; v2(1570,2725) R8.1@1570,2756.38 ; v2(1670,2725) R7.1@1670,2756.38
MCU_VCC_EXT: J23.3 P1.3 | length 262.1
  Signal Layer 3 w40: J23.3@2210,3670 2360,3820 P1.3@2360,3870
MDC: R79.2 R84.2 U2.42 | length 2179.6
  Top Layer w8: R84.2@1643.62,3281.42 v2(1671.9,3281.42) 1692.63,3281.42 cw(c1692.63,3161.73) 1812.31,3161.73 1812.31,2412.69 ccw(c1905,2412.69) 1905,2320 2230.31,2320 cw(c2230.31,2230) 2320.31,2230 2320.31,2000 ccw(c2407.99,2000) 2345.99,1938.01 2388,1896 cw(c2335.27,1843.27) 2409.84,1843.27 2409.84,1840.06 2410.97,1838.93 2410.97,1821.69 2409.84,1820.57 U2.42@2409.84,1773.86
  Bottom Layer w10: R79.2@1620,3356.38 ccw(c1675.68,3356.38) 1636.31,3317.01 v2(1671.9,3281.42)
MDC_F: J15.6 R79.1 | length 406.9
  Bottom Layer w8: R79.1@1620,3403.62 1620,3688.58 cw(c1720,3688.58) 1649.29,3759.29 J15.6@1680,3790
MDC_OB: R84.1 U1.46 | length 74.5
  Top Layer w8: U1.46@1524.53,3291.42 1551.18,3291.42 cw(c1551.18,3274.7) 1563,3286.52 ccw(c1575.32,3298.84) 1575.32,3281.42 R84.1@1596.38,3281.42
MDIO: R75.1 R76.2 R78.2 U2.41 | length 2190.9
  Top Layer w8: R78.2@1643.62,3321.1 v2(1671.9,3321.1) 1732,3321.1 cw(c1732,3221.1) 1832,3221.1 1832,2412.69 ccw(c1905,2412.69) 1905,2339.69 2230.31,2339.69 cw(c2230.31,2230) 2340,2230 2340,2000 ccw(c2407.99,2000) 2359.91,1951.93 2401.92,1909.92 cw(c2335.27,1843.27) 2429.53,1843.27 U2.41@2429.53,1773.86
  Bottom Layer w8: R76.2@1660,3356.38 1660,3349.83 ccw(c1700.62,3349.83) v2(1671.9,3321.1)
MDIO_F: J15.4 R76.1 | length 431.8
  Bottom Layer w8: R76.1@1660,3403.62 1660,3628.58 cw(c1760,3628.58) 1689.29,3699.29 J15.4@1780,3790
MDIO_OB: R78.1 U1.47 | length 74.5
  Top Layer w8: U1.47@1524.53,3311.1 1551.18,3311.1 ccw(c1551.18,3327.82) 1563,3316 cw(c1575.32,3303.68) 1575.32,3321.1 R78.1@1596.38,3321.1
MSP_XIN2: U1.69 Y1.1 | length 177.7
  Top Layer w10: Y1.1@1259.25,3810 1259.25,3745.94 1289.29,3715.91 U1.69@1289.29,3644.76
MSP_XOUT2: R11.2 U1.70 | length 136
  Top Layer w10: R11.2@1188.39,3720 1234.61,3720 1269.61,3685 U1.70@1269.61,3644.76
NetC2_1: C2.1 U1.67 | length 133.5
  Top Layer w10: v2(1314.77,3595) 1328.66,3608.9 U1.67@1328.66,3644.76
  Bottom Layer w10: C2.1@1279.77,3531.5 1279.77,3560 v2(1314.77,3595)
NetC3_1: C3.1 U1.20 | length 73
  Top Layer w10: v2(995,3170) U1.20@995,3192.99
  Bottom Layer w10: C3.1@995,3120 v2(995,3170)
NetC5_1: C5.1 U1.66 | length 113.3
  Top Layer w10: v2(1348.35,3595) U1.66@1348.35,3644.76
  Bottom Layer w10: C5.1@1348.35,3531.5 v2(1348.35,3595)
NetC9_2: C9.2 R15.2 U1.11 | length 127.8
  Top Layer w10: U1.11@995,3370.16 1039.84,3370.16 v2(1040,3370)
  Bottom Layer w10: v2(1040,3370) C9.2@1076.38,3370 R15.2@1076.38,3323.62
NetC13_1: C13.1 R34.1 R39.2 | length 232.9
  Top Layer w6: v2(2047.94,380) R34.1@2077.32,380 ; R39.2@2192.68,380 v2(2222.06,380)
  Bottom Layer w6: v2(2047.94,380) C13.1@2135,380 v2(2222.06,380)
NetC16_1: C16.1 R46.1 R48.2 | length 232.9
  Top Layer w6: v2(2877.94,380) R48.2@2907.31,380 ; R46.1@3022.68,380 v2(3052.06,380)
  Bottom Layer w6: v2(2877.94,380) C16.1@2965,380 v2(3052.06,380)
NetC37_1: C37.1 C39.1 R71.2 | length 80
  Bottom Layer w10: C39.1@2166.38,1429 C37.1@2166.38,1469 R71.2@2166.38,1509
NetC38_1: C38.1 C40.1 R72.2 | length 80
  Bottom Layer w10: R72.2@2166.38,1791 C40.1@2166.38,1831 C38.1@2166.38,1871
NetC41_1: C41.1 R82.1 | length 66.6
  Bottom Layer w12: C41.1@2113.39,1996.61 R82.1@2180,1996.61
NetC45_1: C45.1 R86.1 R91.1 XTAL1.3 | length 178.1
  Top Layer w10: R86.1@2439.53,1425.04 v3(2439.53,1399) 2439.53,1381.78 R91.1@2443.31,1378
  Bottom Layer w10: v3(2439.53,1399) 2439.53,1390 XTAL1.3@2464.96,1364.57 C45.1@2464.96,1280
NetC46_1: C46.1 R89.1 R91.2 XTAL1.1 | length 188
  Top Layer w10: R91.2@2396.06,1378 2399.84,1381.78 v3(2399.84,1401) R89.1@2399.84,1425.04
  Bottom Layer w10: C46.1@2280,1435.43 XTAL1.1@2374.41,1435.43 2399.84,1410 v3(2399.84,1401)
NetC49_2: C49.2 T1.10 | length 113
  Top Layer w10: T1.10@1587.54,1766.42 v2(1649.65,1766.42)
  Bottom Layer w10: C49.2@1649.65,1816.77 v2(1649.65,1766.42) v2@1650,1766.77
NetC51_2: C51.2 T1.7 | length 112.5
  Top Layer w10: T1.7@1587.54,1649.49 v2(1649.65,1649.49)
  Bottom Layer w10: v2(1649.65,1649.49) C51.2@1649.65,1699.84
NetC54_2: C54.2 T1.4 | length 112.5
  Top Layer w10: T1.4@1587.54,1532.56 v2(1649.65,1532.56)
  Bottom Layer w10: v2(1649.65,1532.56) C54.2@1649.65,1582.91
NetC57_2: C57.2 T1.1 | length 112.5
  Top Layer w10: T1.1@1587.54,1415.63 v2(1649.65,1415.63)
  Bottom Layer w10: v2(1649.65,1415.63) C57.2@1649.65,1465.98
